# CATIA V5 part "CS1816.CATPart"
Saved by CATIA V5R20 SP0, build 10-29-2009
Part number: CS1816
Revision: 7
Definition: design
Nomenclature: CS1816
Source: made
Description: NOT SPECIFIED
Bounding box of the stored display mesh (mm): x -15 to 15, y -15 to 15, z -28 to 7.5
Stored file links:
  C:\Users\Raffaele\Desktop\3D X SITO CF\BOLEX\20-TILTED COLUMN SUPPORT\CS1816.CATPart
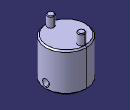
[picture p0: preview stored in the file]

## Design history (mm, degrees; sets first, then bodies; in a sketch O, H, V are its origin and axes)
Body1 "MANIFOLD_SOLID_BREP #691" (main body)
  Solid1: solid without history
